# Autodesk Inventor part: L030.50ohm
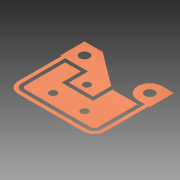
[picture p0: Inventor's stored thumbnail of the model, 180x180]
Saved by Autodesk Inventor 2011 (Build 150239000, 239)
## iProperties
Created: 2014-06
Part Number: L030.50ohm
Document SubType Name: Modeling
Designer: Evgeny
Density: 1 g/cm^3
Author: Evgeny
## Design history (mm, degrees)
sketch "Эскиз2"
  geometry: L1 (18.5, 6)-(18.5, 16); L2 (-18.5, 16)-(-18.5, 6); L3 (-7, 6)-(-7, -2); L4 (-7, -2)-(3, -2); L5 (3, -2)-(3, 5.5); L6 (3, 5.5)-(-11, 16); L7 (-18, 6)-(-18, -12); L8 (-13.5, -16.5)-(13.5, -16.5); L9 (18, -12)-(18, 6); L10 (18, 6)-(18.5, 6); L11 (16.5, 6)-(13.5, 6); L12 (8.5, 11)-(8.5, 11); L13 (16.5, 6)-(16.5, -12); L14 (13.5, -15)-(-13.5, -15); L15 (-16.5, -12)-(-16.5, 6); L16 (-15, 4.5)-(-8.5, 4.5); L17 (-8.5, 4.5)-(-8.5, -3.5); L18 (-8.5, -3.5)-(4.5, -3.5); L19 (4.5, -3.5)-(4.5, 4.5); L20 (4.5, 4.5)-(15, 4.5); L21 (15, 4.5)-(15, -12); L22 (13.5, -13.5)-(-13.5, -13.5); L23 (-15, -12)-(-15, 4.5); L24 (-18.5, 6)-(-18, 6); L25 (-16.5, 6)-(-7, 6); L26 (18.5, 16)-(13.5, 16); L27 (-11, 16)-(-18.5, 16); C1 r 2 at (-13.5, 11); C2 r 2 at (13.5, 11); C3 r 1.5 at (-2.5, 1); C4 r 1.5 at (-6.5, -9); C5 r 1.5 at (6.5, -9); A1 r 5 centre (13.5, 11) between (8.5, 11) and (13.5, 6); A2 r 5 centre (13.5, 11) between (13.5, 16) and (8.5, 11); A3 r 1.5 centre (-13.5, -12) between (-15, -12) and (-13.5, -13.5); A4 r 1.5 centre (13.5, -12) between (13.5, -13.5) and (15, -12); A5 r 3 centre (-13.5, -12) between (-16.5, -12) and (-13.5, -15); A6 r 3 centre (13.5, -12) between (13.5, -15) and (16.5, -12); A7 r 4.5 centre (-13.5, -12) between (-18, -12) and (-13.5, -16.5); A8 r 4.5 centre (13.5, -12) between (13.5, -16.5) and (18, -12); 1 further point
  constraints: 54 end point, 16 point on circle, 16 tangent, 14 perpendicular, 13 centre point, 11 parallel, 6 collinear, 4 equal radius
  dimensions: "d1" = 37 distance between parallel lines of L1 L2; "d5" = 0.5 distance between parallel lines of L7 L2; "d6" = 0.5 distance between parallel lines of L9 L1; "d8" = 1.5 distance between parallel lines of L15 L7; "d9" = 1.5 distance between parallel lines of L14 L8; "d10" = 1.5 distance between parallel lines of L13 L9; "d11" = 1.5 distance between parallel lines of L23 L15; "d12" = 1.5 distance between parallel lines of L22 L14; "d13" = 1.5 distance between parallel lines of L21 L13; "d14" = 1.5 distance between parallel lines of L16 L25; "d15" = 11.5 distance between parallel lines of L3 L2; "d16" = 1.5 distance between parallel lines of L17 L3; "d17" = 7.5 distance from line of L6.end L2; "d18" = 21.5 distance between parallel lines of L5 L2; "d20" = 1.5 distance between parallel lines of L18 L4; "d21" = 1.5 distance between parallel lines of L19 L5; "d22" = 4 diameter of C1; "d23" = 4 diameter of C2; "d24" = 3 diameter of C3; "d25" = 3 diameter of C4; "d26" = 3 diameter of C5; "d27" = 27 distance of C2.centre C1.centre; "d28" = 13.5 horizontal distance of point (0, 0) C2.centre; "d31" = 10 distance between parallel lines of L12 L1; "d33" = 16 distance from line of L2 C3.centre; "d35" = 13 distance of C5.centre C4.centre; "d36" = 6.5 horizontal distance of C5.centre point (0, 0); "d37" = 32.5 distance between parallel lines of L8 L27; "d38" = 25 distance from line of C4.centre L27; "d39" = 18 distance between parallel lines of L4 L27; "d40" = 10 distance between parallel lines of L25 L27; "d41" = 5 distance from line of C1.centre L27; "d42" = 15 distance from line of C3.centre L26; "d43" = 5 radius of A1; "d44" = 1.5 radius of A3; "d45" = 3 radius of A5; "d46" = 4.5 radius of A7
extrude "Выдавливание1" new body sketch "Эскиз2" distance "d47" = 0.05; taper "d48" = 0 deg
node "Твердое тело1"
other parameters: "d7" = 32.5, "d19" = 18, "d29" = 5, "d30" = 5, "d32" = 15, "d34" = 25
